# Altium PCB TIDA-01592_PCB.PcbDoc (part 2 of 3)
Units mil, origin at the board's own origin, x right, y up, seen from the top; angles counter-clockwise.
Board outline 2047.24 x 4291.34 mil, 4 copper layers (Top Layer, GND, PWR, Bottom Layer), stack 61.6 mil thick; 218 components, 89 nets, 503 pads, 366 vias.
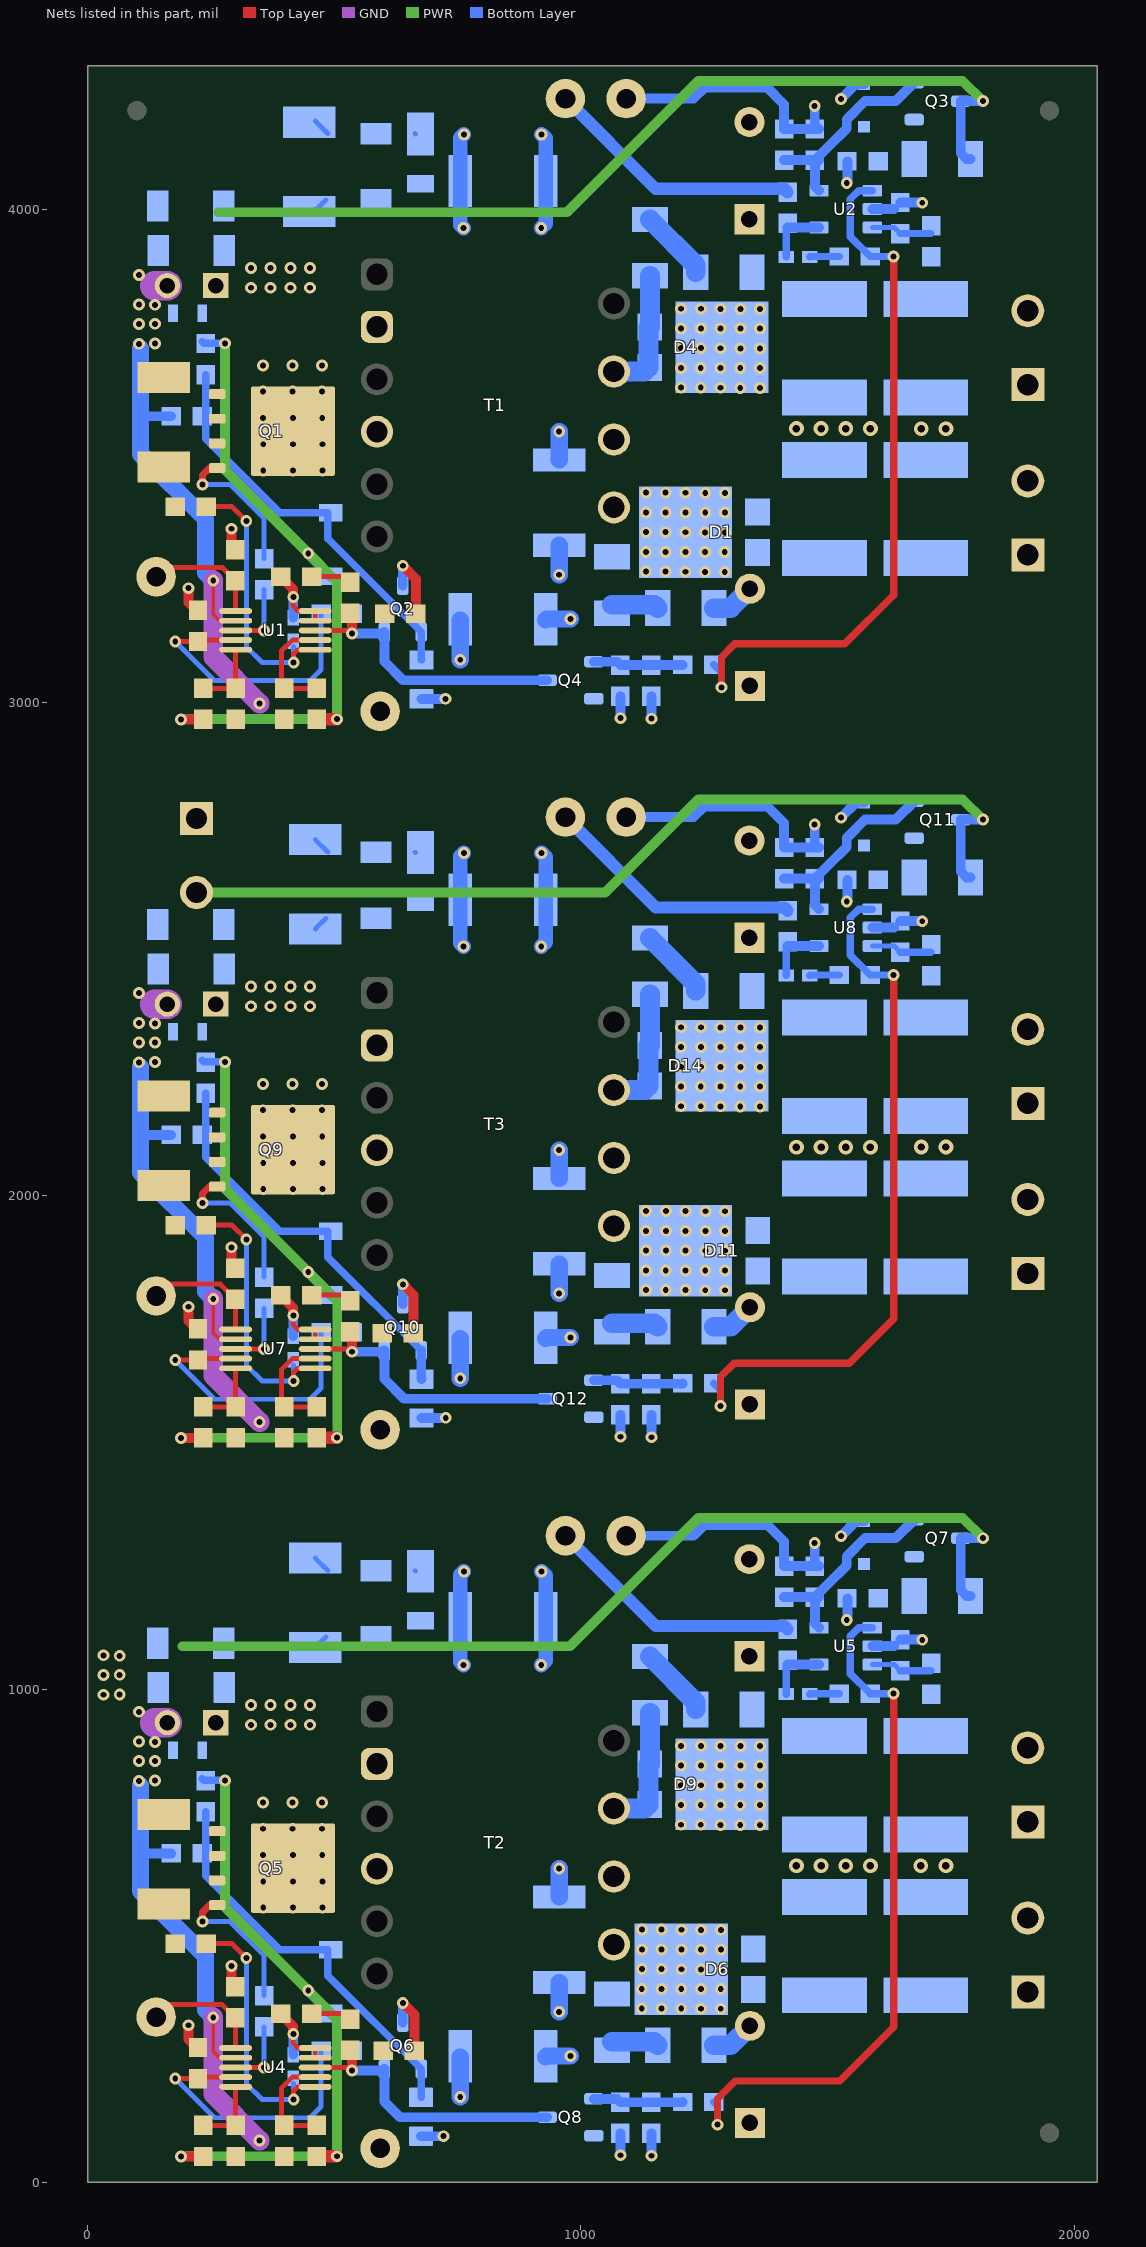
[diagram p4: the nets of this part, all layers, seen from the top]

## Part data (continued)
U2 U5 U8: "36V, Low-Power, RRO, General-Purpose Operational Amplifier, DBV0005A (SOT-23-5)", Alternate Manufacturer="Texas Instruments", Alternate PartNumber=TLV171IDBVT
ZZ1: library part AssemblyNoteLabel, Alternate Manufacturer=-
ZZ2 ZZ3 ZZ4: library part AssemblyNote, Alternate Manufacturer=-

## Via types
v1: diameter 24, hole 12, Top Layer to Bottom Layer, 348 vias
v2: diameter 30, hole 15, Top Layer to Bottom Layer, 18 vias

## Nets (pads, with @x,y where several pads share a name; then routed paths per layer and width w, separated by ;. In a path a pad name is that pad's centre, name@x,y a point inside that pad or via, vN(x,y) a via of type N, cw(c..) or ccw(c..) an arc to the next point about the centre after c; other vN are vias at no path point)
+Vo1: C31.1 C32.2 C33.2 C34.1 D9.3 J6.1 R39.2
  other v1: 1323.06,724.67 1363.06,724.67 1202.94,725 1242.94,725 1283,724.83 1323.06,764.67 1363.06,764.67 1202.94,765 1242.94,765 1283,764.83 1323.22,804.73 1363.22,804.73 1203.11,805.05 1243.11,805.05 1283.16,804.89 1203.27,845.11 1243.27,845.11 1283.32,844.94 1323.38,844.78 1363.38,844.78 1203.27,885.11 1243.27,885.11 1283.32,884.94 1323.38,884.78 1363.38,884.78
+Vo2: C52.1 C53.2 C54.2 C55.1 D14.3 J9.1 R68.2
  other v1: 1202.94,2181.69 1242.94,2181.69 1283,2181.53 1323.06,2181.37 1363.06,2181.37 1202.94,2221.69 1242.94,2221.69 1283,2221.53 1323.06,2221.37 1363.06,2221.37 1203.11,2261.74 1243.11,2261.74 1283.16,2261.58 1323.22,2261.42 1363.22,2261.42 1283.32,2301.64 1323.38,2301.48 1363.38,2301.48 1203.27,2301.8 1243.27,2301.8 1283.32,2341.64 1323.38,2341.48 1363.38,2341.48 1203.27,2341.8 1243.27,2341.8
+Vo3: C10.1 C11.2 C12.2 C13.1 D4.3 J3.1 R10.2
  other v1: 1202.94,3638.38 1242.94,3638.38 1283,3638.22 1323.06,3638.06 1363.06,3638.06 1202.94,3678.38 1242.94,3678.38 1283,3678.22 1323.06,3678.06 1363.06,3678.06 1203.11,3718.44 1243.11,3718.44 1283.16,3718.28 1323.22,3718.11 1363.22,3718.11 1203.27,3758.49 1243.27,3758.49 1283.32,3758.33 1323.38,3758.17 1363.38,3758.17 1203.27,3798.49 1243.27,3798.49 1283.32,3798.33 1323.38,3798.17 1363.38,3798.17
GND: C2.2 C3.2 C4.2 C9.1 C14.2 C18.2 C19.2 C20.1 C21.2 C23.2 C24.2 C25.2 C30.1 C35.2 C39.2 C40.2 C42.2 C44.2 C45.2 C46.2 C51.1 C56.2 C60.2 C61.2 C62.1 C63.2 C68.1 J1.1 Q2.3 Q6.3 Q10.3 R2.1 R8.1 R13.1 R14.1 R17.1 R20.1 R21.1 R25.1 R27.1 R31.1 R37.1 R42.1 R43.1 R49.1 R56.1 R60.1 R66.1 R71.1 R72.1 R78.1 R85.1 TP2.1 TP6.1 TP10.1 U1.4 U1.5 U1.7 U4.4 U4.5 U4.7 U7.4 U7.5 U7.7 | length 5332.4
  Top Layer w8: v1(254.69,334.05) 254.69,265.01 265.11,254.59 298.13,254.59 U4.7@300.03,252.68 ; v1(254.69,1790.74) 254.69,1721.7 265.11,1711.28 298.13,1711.28 U7.7@300.03,1709.38 ; v1(254.69,3247.43) 254.69,3178.39 265.11,3167.98 298.13,3167.98 U1.7@300.03,3166.07
  Top Layer w10: v1@416.68,301 416.68,282.32 426.63,272.37 U4.5@461.45,272.37 U4.4@461.45,252.68 ; v1@416.68,1757.69 416.68,1739.02 426.63,1729.06 U7.5@461.45,1729.06 U7.4@461.45,1709.38 ; v1@416.68,3214.39 416.68,3195.71 426.63,3185.76 U1.5@461.45,3185.76 U1.4@461.45,3166.07
  Top Layer w20: v1(204.26,318.5) 204.26,289.74 C40.2@220,274 ; v1(204.26,1775.2) 204.26,1746.43 C61.2@220,1730.69 ; v1(204.26,3231.89) 204.26,3203.13 C19.2@220,3187.39 ; v1(291.74,439) 291.74,404.5 R43.1@299.74,396.5 ; v1(291.74,1895.69) 291.74,1861.19 R72.1@299.74,1853.19 ; v1(291.74,3352.39) 291.74,3317.88 R14.1@299.74,3309.88 ; C30.1@300.74,52.5 C30.1@301.24,52 ; C51.1@300.74,1509.2 C51.1@301.24,1508.69 ; C9.1@300.74,2965.89 C9.1@301.24,2965.39 ; C42.2@391.24,342 416.68,316.57 416.68,301 v1(417,301) ; C63.2@391.24,1798.69 416.68,1773.26 416.68,1757.69 v1(417,1757.69) ; C21.2@391.24,3255.39 416.68,3229.95 416.68,3214.39 v1(417,3214.39) ; R37.1@398.24,52 R37.1@398.74,52.5 ; R66.1@398.24,1508.69 R66.1@398.74,1509.2 ; R8.1@398.24,2965.39 R8.1@398.74,2965.89 ; v1(639,364) 662.5,340.5 C62.1@662.5,267 ; v1(639,1820.69) 660.5,1799.2 C68.1@660.5,1721 ; v1(639,3277.39) 665.5,3250.89 C20.1@665.5,3180
  GND w40: v1(254.69,334.05) 254.69,179.05 v1(348.74,85) ; v1(254.69,1790.74) 254.69,1635.74 v1(348.74,1541.69) ; v1(254.69,3247.43) 254.69,3092.43 v1(348.74,2998.39)
  GND w60: C23.2@136.5,932 C23.2@161.53,932 ; C44.2@136.5,2388.69 C44.2@161.53,2388.69 ; C2.2@136.5,3845.39 C2.2@161.53,3845.39
  Bottom Layer w20: 107,666 108,667 R21.1@169.5,667 ; 107,2122.69 108,2123.69 R25.1@169.5,2123.69 ; 107,3579.39 108,3580.39 R17.1@169.5,3580.39 ; C39.2@417,258.62 v1(417,301) ; C60.2@417,1715.31 v1(417,1757.69) ; C18.2@417,3172.01 v1(417,3214.39) ; Q6.3@639,324.24 v1(639,364) ; Q10.3@639,1780.94 v1(639,1820.69) ; Q2.3@639,3237.63 v1(639,3277.39) ; C35.2@676,93.63 v1(721.63,93.63) ; C56.2@677,1549.63 684.37,1549.63 684.74,1550 v1(726,1550) ; C14.2@677,3007.63 v1(725.37,3007.63)
  Bottom Layer w30: v1(761.74,1049) 755.39,1055.35 R49.1@755.39,1144 755.39,1231.15 v1(762.74,1238.5) ; v1(761.74,2505.69) 755.39,2512.05 R78.1@755.39,2600.69 755.39,2687.84 v1(762.74,2695.2) ; v1(761.74,3962.39) 755.39,3968.74 R20.1@755.39,4057.39 755.39,4144.54 v1(762.74,4151.89)
  Bottom Layer w35: v1@107,804 107,666 107,590.74 239,458.74 239,349.74 v1(254.69,334.05) ; v1@107,2260.69 107,2122.69 107,2047.43 239,1915.43 239,1806.43 v1(254.69,1790.74) ; v1@107,3717.39 107,3579.39 107,3504.13 239,3372.13 239,3263.13 v1(254.69,3247.43) ; v1(755.39,173.39) R56.1@755.39,254 ; v1(755.39,1630.08) R85.1@755.39,1710.69 ; v1(755.39,3086.77) R27.1@755.39,3167.39
  other v1: 104,814 136.5,814.5 104,854 136.5,854.5 136.5,893 104,894 104,954 32.5,988.5 65,989 32.5,1028.5 65,1029 65,1067.5 32.5,1068.5 104,2270.69 136.5,2271.19 104,2310.69 136.5,2311.19 136.5,2349.69 104,2350.69 104,2411 104,3727.39 136.5,3727.88 104,3767.39 136.5,3767.88 136.5,3806.39 104,3807.39 104,3867
NetC1_1: C1.1 C5.1 C6.1 C7.2 D1.1 D1.2 J2.2 | length 89
  Bottom Layer w40: C1.1@1270.09,3191.39 1303.31,3191.39 C7.2@1342.74,3230.81
NetC1_2: C1.2 R1.2 | length 95.8
  Bottom Layer w40: R1.2@1063,3198.39 1148.91,3198.39 C1.2@1155.91,3191.39
NetC8_2: C8.2 D2.1 R3.1 | length 37.3
  Bottom Layer w10: R3.1@461.74,4178.94 R3.1@487.36,4153.31 ; D2.1@664.01,4153.31 D2.1@664.74,4152.58
NetC9_2: C9.2 R5.2 U1.10 | length 144.4
  Top Layer w10: R5.2@234.74,3028.88 C9.2@300.74,3028.88 300.03,3029.59 U1.10@300.03,3107.02
NetC10_2: C10.2 R7.2 | length 145.6
  Bottom Layer w40: R7.2@1140,3979.47 1232.91,3886.56 C10.2@1232.91,3872.39
NetC14_1: C14.1 D3.2 Q2.1 R6.1 R17.2 | length 816.8
  Bottom Layer w15: R6.1@239.71,3664.92 239.71,3534.68 389.53,3384.85 487,3384.85 487,3332.54 Q2.1@676.4,3143.14 676.4,3086.97 C14.1@677,3086.37
NetC15_1: C15.1 R28.1 U2.1 | length 1433
  Top Layer w15: v1(1285,3031) 1285,3092 1312,3119 1535,3119 1634,3218 v1(1634,3904.39)
  Bottom Layer w15: R28.1@1269.5,3076.39 1285,3060.88 v1(1285,3031) ; U2.1@1591.06,4037.98 1563.34,4037.98 1546.24,4020.88 1546.24,3944.65 C15.1@1586.5,3904.39 v1(1634,3904.39)
NetC15_2: C15.2 R19.1 | length 60.3
  Bottom Layer w15: R19.1@1463.62,3903.39 1464.62,3904.39 C15.2@1523.5,3904.39
NetC18_1: C18.1 R11.1 U1.1 | length 562.3
  Top Layer w10: R11.1@240.24,3397.39 R11.1@245.24,3397.39 ; R11.1@240.24,3402.39 R11.1@245.24,3397.39 ; v1(321.74,3368.39) 292.74,3397.39 R11.1@245.24,3397.39 ; v1(417.74,3081.39) 417.74,3099.39 425.37,3107.02 U1.1@461.45,3107.02
  Bottom Layer w10: v1(321.74,3368.39) 321.74,3113.39 353.74,3081.39 v1(417.74,3081.39) C18.1@417.74,3114.02
NetC19_1: C19.1 R12.2 U1.9 | length 574.7
  Top Layer w10: v1(177.74,3123.89) C19.1@223.74,3123.89 226.55,3126.7 U1.9@300.03,3126.7
  Bottom Layer w10: v1(177.74,3123.89) 257.24,3044.39 450.74,3044.39 473.24,3066.89 R12.2@473.24,3180.39
NetC20_2: C20.2 Q2.2 Q4.3 R12.1 R18.2 U1.3 | length 631
  Top Layer w10: U1.3@461.45,3146.39 v1@533.47,3146.39 ; R18.2@529.74,3190.89 R18.2@531.74,3192.89
  Top Layer w20: R18.2@532,3180.89 536.24,3176.65 536,3176.42 v1(536,3140)
  Bottom Layer w20: R12.1@536.24,3180.39 536,3180.15 v1(536,3140) 597.5,3140 601.12,3143.62 Q2.2@601.6,3143.14 601.6,3083.4 639.61,3045.39 Q4.3@931.76,3045.39
NetC21_1: C21.1 R18.1 | length 77.7
  Top Layer w10: C21.1@454.24,3255.39 454.73,3255.88 R18.1@531.74,3255.88
NetC22_1: C22.1 C26.1 C27.1 C28.2 D6.1 D6.2 J5.2 | length 89
  Bottom Layer w40: C22.1@1270.09,278 1303.31,278 C28.2@1342.74,317.43
NetC22_2: C22.2 R30.2 | length 95.8
  Bottom Layer w40: R30.2@1063,285 1148.91,285 C22.2@1155.91,278
NetC29_2: C29.2 D7.1 R32.1 | length 37.3
  Bottom Layer w10: R32.1@461.74,1265.55 R32.1@487.36,1239.93 ; D7.1@664.01,1239.93 D7.1@664.74,1239.2
NetC30_2: C30.2 R34.2 U4.10 | length 144.4
  Top Layer w10: R34.2@234.74,115.5 C30.2@300.74,115.5 300.03,116.2 U4.10@300.03,193.63
NetC31_2: C31.2 R36.2 | length 145.6
  Bottom Layer w40: R36.2@1140,1066.09 1232.91,973.17 C31.2@1232.91,959
NetC35_1: C35.1 D8.2 Q6.1 R21.2 R35.1 | length 817.3
  Bottom Layer w15: R35.1@239.71,751.54 239.71,621.29 389.53,471.47 487,471.47 487,419.16 Q6.1@676.4,229.76 676,229.35 C35.1@676,172.37
NetC36_1: C36.1 R57.1 U5.1 | length 1427.5
  Top Layer w15: v1(1277,117) 1277,169.54 1313.07,205.62 1524.62,205.62 1634,315 v1(1634,991)
  Bottom Layer w15: R57.1@1269.5,163 1277,155.5 v1(1277,117) ; U5.1@1591.06,1124.6 1563.34,1124.6 1546.24,1107.5 1546.24,1031.26 C36.1@1586.5,991 v1(1634,991)
NetC36_2: C36.2 R23.1 | length 60.3
  Bottom Layer w15: R23.1@1463.62,990 1464.62,991 C36.2@1523.5,991
NetC39_1: C39.1 R40.1 U4.1 | length 562.3
  Top Layer w10: R40.1@240.24,484 R40.1@245.24,484 ; R40.1@240.24,489 R40.1@245.24,484 ; v1(321.74,455) 292.74,484 R40.1@245.24,484 ; v1(417.74,168) 417.74,186 425.37,193.63 U4.1@461.45,193.63
  Bottom Layer w10: v1(321.74,455) 321.74,200 353.74,168 v1(417.74,168) C39.1@417.74,200.64
NetC40_1: C40.1 R41.2 U4.9 | length 574.7
  Top Layer w10: v1(177.74,210.5) C40.1@223.74,210.5 226.55,213.31 U4.9@300.03,213.31
  Bottom Layer w10: v1(177.74,210.5) 257.24,131 450.74,131 473.24,153.5 R41.2@473.24,267
NetC41_2: C41.2 Q4.1 R28.2 R29.1 | length 183.3
  Bottom Layer w20: Q4.1@1026.24,3082.79 1073.09,3082.79 R29.1@1080,3075.88 C41.2@1143,3075.88 1206,3075.88 R28.2@1206.5,3076.39
NetC42_1: C42.1 R47.1 | length 77.7
  Top Layer w10: C42.1@454.24,342 454.73,342.5 R47.1@531.74,342.5
NetC43_1: C43.1 C47.1 C48.1 C49.2 D11.1 D11.2 J8.2 | length 89
  Bottom Layer w40: C43.1@1270.09,1734.69 1303.31,1734.69 C49.2@1342.74,1774.12
NetC43_2: C43.2 R59.2 | length 95.8
  Bottom Layer w40: R59.2@1063,1741.69 1148.91,1741.69 C43.2@1155.91,1734.69
NetC50_2: C50.2 D12.1 R61.1 | length 37.3
  Bottom Layer w10: R61.1@461.74,2722.24 R61.1@487.36,2696.62 ; D12.1@664.01,2696.62 D12.1@664.74,2695.89
NetC51_2: C51.2 R63.2 U7.10 | length 144.4
  Top Layer w10: R63.2@234.74,1572.19 C51.2@300.74,1572.19 300.03,1572.9 U7.10@300.03,1650.32
NetC52_2: C52.2 R65.2 | length 145.6
  Bottom Layer w40: R65.2@1140,2522.78 1232.91,2429.87 C52.2@1232.91,2415.69
NetC56_1: C56.1 D13.2 Q10.1 R25.2 R64.1 | length 818.1
  Bottom Layer w15: R64.1@239.71,2208.23 239.71,2077.98 389.53,1928.16 487,1928.16 487,1875.85 Q10.1@676.4,1686.45
  Bottom Layer w20: Q10.1@676.4,1686.45 676.4,1628.97 C56.1@677,1628.37
NetC57_1: C57.1 R86.1 U8.1 | length 1439.4
  Top Layer w15: v1(1283,1574) 1283,1633 1311,1661 1544,1661 1634,1751 v1(1634,2447.69)
  Bottom Layer w15: R86.1@1269.5,1619.69 1283,1606.19 v1(1283,1574) ; U8.1@1591.06,2581.29 1563.34,2581.29 1546.24,2564.19 1546.24,2487.95 C57.1@1586.5,2447.69 v1(1634,2447.69)
NetC57_2: C57.2 R26.1 | length 60.3
  Bottom Layer w15: R26.1@1463.62,2446.69 1464.62,2447.69 C57.2@1523.5,2447.69
NetC60_1: C60.1 R69.1 U7.1 | length 562.3
  Top Layer w10: R69.1@240.24,1940.69 R69.1@245.24,1940.69 ; R69.1@240.24,1945.69 R69.1@245.24,1940.69 ; v1(321.74,1911.69) 292.74,1940.69 R69.1@245.24,1940.69 ; v1(417.74,1624.69) 417.74,1642.69 425.37,1650.32 U7.1@461.45,1650.32
  Bottom Layer w10: v1(321.74,1911.69) 321.74,1656.69 353.74,1624.69 v1(417.74,1624.69) C60.1@417.74,1657.33
NetC61_1: C61.1 R70.2 U7.9 | length 574.7
  Top Layer w10: v1(177.74,1667.2) C61.1@223.74,1667.2 226.55,1670.01 U7.9@300.03,1670.01
  Bottom Layer w10: v1(177.74,1667.2) 257.24,1587.69 450.74,1587.69 473.24,1610.2 R70.2@473.24,1723.69
NetC62_2: C62.2 Q6.2 Q8.3 R41.1 R47.2 U4.3 | length 634
  Top Layer w10: U4.3@461.45,233 v1@533.47,233 ; R47.2@529.74,277.5 R47.2@531.74,279.5
  Top Layer w20: R47.2@532,267.5 536.24,263.27 536,263.03 v1(536,227)
  Bottom Layer w20: R41.1@536.24,267 536,266.76 v1(536,227) 597.88,227 601.12,230.24 Q6.2@601.6,229.76 601.6,163.4 633,132 Q8.3@931.76,132
NetC63_1: C63.1 R76.1 | length 77.7
  Top Layer w10: C63.1@454.24,1798.69 454.73,1799.19 R76.1@531.74,1799.19
NetC64_1: C64.1 D5.1 Q3.1 R22.1
NetC65_1: C65.1 D10.1 Q7.1 R51.1
NetC66_1: C66.1 D15.1 Q11.1 R80.1
NetC67_2: C67.2 Q8.1 R57.2 R58.1 | length 183.3
  Bottom Layer w20: Q8.1@1026.24,169.4 1073.09,169.4 R58.1@1080,162.5 C67.2@1143,162.5 1206,162.5 R57.2@1206.5,163
NetC68_2: C68.2 Q10.2 Q12.3 R70.1 R76.2 U7.3 | length 628.4
  Top Layer w10: U7.3@461.45,1689.69 v1@533.47,1689.69 ; R76.2@529.74,1734.2 R76.2@531.74,1736.2
  Top Layer w20: R76.2@532,1724.2 536.24,1719.96 536,1719.72 v1(536,1684)
  Bottom Layer w20: R70.1@536.24,1723.69 536,1723.46 v1(536,1684) 598.19,1684 601.12,1686.93 Q10.2@601.6,1686.45 601.6,1628.4 641.31,1588.69 Q12.3@931.76,1588.69
NetC69_2: C69.2 Q12.1 R86.2 R87.1 | length 183.3
  Bottom Layer w20: Q12.1@1026.24,1626.09 1073.09,1626.09 R87.1@1080,1619.19 C69.2@1143,1619.19 1206,1619.19 R86.2@1206.5,1619.69
NetD1_3: D1.3 R1.1 T1.7
  other v1: 1131.62,3265.44 1171.62,3265.44 1211.68,3265.28 1251.73,3265.11 1291.73,3265.11 1131.62,3305.44 1171.62,3305.44 1211.68,3305.28 1251.73,3305.11 1291.73,3305.11 1131.78,3345.49 1171.78,3345.49 1211.84,3345.33 1251.89,3345.17 1291.89,3345.17 1131.94,3385.55 1171.94,3385.55 1212,3385.39 1252.06,3385.22 1292.06,3385.22 1131.94,3425.55 1171.94,3425.55 1212,3425.39 1252.06,3425.22 1292.06,3425.22
NetD2_2: D2.2 Q1.5 Q1.6 Q1.7 Q1.8 Q1.9@416.26,3550.39 T1.4
  other v1: 356,3470.39 416.26,3470.39 476,3470.39 356,3523.72 416.26,3523.72 476,3523.72 355.74,3577.05 416,3577.05 475.74,3577.05 355.48,3630.39 415.74,3630.39 475.48,3630.39 355.22,3683.72 415.48,3683.72 475.22,3683.72
NetD4_1: D4.1 D4.2 R7.1 T1.9 | length 259.4
  Bottom Layer w40: T1.9@1066.93,3671.26 1128.76,3671.26 1137,3679.5 D4.1@1137,3761.39 ; D4.1@1139.95,3761.33 1139.95,3865.25 R7.1@1140,3865.3
NetD6_3: D6.3 R30.1 T2.7
  other v1: 1123.38,352.26 1163.38,352.26 1203.43,352.09 1243.49,351.93 1283.49,351.93 1123.38,392.26 1163.38,392.26 1203.43,392.09 1243.49,391.93 1283.49,391.93 1123.54,432.31 1163.54,432.31 1203.59,432.15 1243.65,431.99 1283.65,431.99 1123.7,472.37 1163.7,472.37 1203.76,472.2 1243.81,472.04 1283.81,472.04 1123.7,512.37 1163.7,512.37 1203.76,512.2 1243.81,512.04 1283.81,512.04
NetD7_2: D7.2 Q5.5 Q5.6 Q5.7 Q5.8 Q5.9@416.26,637 T2.4
  other v1: 356,557 416.26,557 476,557 356,610.33 416.26,610.33 476,610.33 355.74,663.67 416,663.67 475.74,663.67 355.48,717 415.74,717 475.48,717 355.22,770.33 415.48,770.33 475.22,770.33
NetD9_1: D9.1 D9.2 R36.1 T2.9 | length 259.4
  Bottom Layer w40: T2.9@1066.93,757.87 1128.76,757.87 1137,766.11 D9.1@1137,848 ; D9.1@1139.95,847.94 1139.95,951.87 R36.1@1140,951.91
NetD11_3: D11.3 R59.1 T3.7
  other v1: 1252.11,1808.68 1292.11,1808.68 1132,1809 1172,1809 1212.06,1808.84 1252.11,1848.68 1292.11,1848.68 1132,1849 1172,1849 1212.06,1848.84 1252.27,1888.73 1292.27,1888.73 1132.16,1889.06 1172.16,1889.06 1212.22,1888.89 1132.32,1929.11 1172.32,1929.11 1212.38,1928.95 1252.43,1928.79 1292.43,1928.79 1132.32,1969.11 1172.32,1969.11 1212.38,1968.95 1252.43,1968.79 1292.43,1968.79
NetD12_2: D12.2 Q9.5 Q9.6 Q9.7 Q9.8 Q9.9@416.26,2093.69 T3.4
  other v1: 356,2013.69 416.26,2013.69 476,2013.69 356,2067.03 416.26,2067.03 476,2067.03 355.74,2120.36 416,2120.36 475.74,2120.36 355.48,2173.69 415.74,2173.69 475.48,2173.69 355.22,2227.03 415.48,2227.03 475.22,2227.03
NetD14_1: D14.1 D14.2 R65.1 T3.9 | length 259.4
  Bottom Layer w40: T3.9@1066.93,2214.57 1128.76,2214.57 1137,2222.8 D14.1@1137,2304.69 ; D14.1@1139.95,2304.64 1139.95,2408.56 R65.1@1140,2408.61
NetQ1_1: Q1.1 Q1.2 Q1.3 R11.2 R13.2
NetQ1_4: Q1.4 R9.2 | length 288.9
  Top Layer w15: v1(233,3442.39) 233,3461.39 247,3475.39 Q1.4@262.72,3475.39
  Bottom Layer w10: v1(233,3442.39) 288,3442.39 357.74,3372.65 R9.2@357.74,3291.88
NetQ5_1: Q5.1 Q5.2 Q5.3 R40.2 R42.2
NetQ5_4: Q5.4 R38.2 | length 288.9
  Top Layer w15: v1(233,529) 233,548 247,562 Q5.4@262.72,562
  Bottom Layer w10: v1(233,529) 288,529 357.74,459.26 R38.2@357.74,378.5
NetQ9_1: Q9.1 Q9.2 Q9.3 R69.2 R71.2
NetQ9_4: Q9.4 R67.2 | length 288.9
  Top Layer w15: v1(233,1985.69) 233,2004.69 247,2018.69 Q9.4@262.72,2018.69
  Bottom Layer w10: v1(233,1985.69) 288,1985.69 357.74,1915.95 R67.2@357.74,1835.19
NetR4_1: R4.1 R8.2 U1.2 | length 221.8
  Top Layer w10: U1.2@461.45,3126.7 415.06,3126.7 392.87,3104.51 392.87,3034.76 R8.2@398.74,3028.88 R4.1@464.74,3028.88
NetR9_1: R9.1 U1.8 | length 140.2
  Top Layer w10: U1.8@300.03,3146.39 v1(357.74,3146.39)
  Bottom Layer w10: v1(357.74,3146.39) R9.1@357.74,3228.89
NetR10_1: R10.1 R16.1 U2.3 | length 123.8
  Bottom Layer w10: U2.3@1591.06,3963.18 1635.45,3963.18 R16.1@1647.74,3950.89
  Bottom Layer w15: R16.1@1647.74,3950.89 R10.1@1709.74,3950.89
NetR14_2: R14.2 TP1.1 U1.6 | length 241.1
  Top Layer w10: TP1.1@139,3255 158,3274 272.63,3274 R14.2@299.74,3246.89 300.03,3246.6 U1.6@300.03,3185.76
NetR15_1: R15.1 R19.2 U2.4 | length 124.7
  Bottom Layer w15: R19.2@1416.38,3903.39 1416.38,3960.53 R15.1@1418.74,3962.89
  Bottom Layer w20: R15.1@1418.74,3962.89 1419.03,3963.18 U2.4@1482.79,3963.18
NetR23_2: R23.2 R44.1 U5.4 | length 124.7
  Bottom Layer w15: R23.2@1416.38,990 1416.38,1047.14 R44.1@1418.74,1049.5
  Bottom Layer w20: R44.1@1418.74,1049.5 1419.03,1049.79 U5.4@1482.79,1049.79
NetR26_2: R26.2 R73.1 U8.4 | length 124.7
  Bottom Layer w15: R26.2@1416.38,2446.69 1416.38,2503.83 R73.1@1418.74,2506.2
  Bottom Layer w20: R73.1@1418.74,2506.2 1419.03,2506.49 U8.4@1482.79,2506.49
NetR33_1: R33.1 R37.2 U4.2 | length 221.8
  Top Layer w10: U4.2@461.45,213.31 415.06,213.31 392.87,191.13 392.87,121.37 R37.2@398.74,115.5 R33.1@464.74,115.5
NetR38_1: R38.1 U4.8 | length 140.2
  Top Layer w10: U4.8@300.03,233 v1(357.74,233)
  Bottom Layer w10: v1(357.74,233) R38.1@357.74,315.5
NetR39_1: R39.1 R45.1 U5.3 | length 123.8
  Bottom Layer w10: U5.3@1591.06,1049.79 1635.45,1049.79 R45.1@1647.74,1037.5
  Bottom Layer w15: R45.1@1647.74,1037.5 R39.1@1709.74,1037.5
NetR43_2: R43.2 TP5.1 U4.6 | length 244.2
  Top Layer w10: TP5.1@139,335 165,361 272.24,361 R43.2@299.74,333.5 300.03,333.21 U4.6@300.03,272.37
NetR62_1: R62.1 R66.2 U7.2 | length 221.8
  Top Layer w10: U7.2@461.45,1670.01 415.06,1670.01 392.87,1647.82 392.87,1578.06 R66.2@398.74,1572.19 R62.1@464.74,1572.19
NetR67_1: R67.1 U7.8 | length 140.2
  Top Layer w10: U7.8@300.03,1689.69 v1(357.74,1689.69)
  Bottom Layer w10: v1(357.74,1689.69) R67.1@357.74,1772.2
NetR68_1: R68.1 R74.1 U8.3 | length 123.8
  Bottom Layer w10: U8.3@1591.06,2506.49 1635.45,2506.49 R74.1@1647.74,2494.2
  Bottom Layer w15: R74.1@1647.74,2494.2 R68.1@1709.74,2494.2
NetR72_2: R72.2 TP9.1 U7.6 | length 244.7
  Top Layer w10: TP9.1@139,1797 162.97,1820.97 268.97,1820.97 R72.2@299.74,1790.2 300.03,1789.91 U7.6@300.03,1729.06
PWRGND01: C37.2 C38.2 C65.2 C67.1 D10.2 Q8.2 R45.2 R53.1 R56.2 R58.2 TP8.1 U5.2 | length 916.4
  Bottom Layer w10: R45.2@1634.44,1087.2 R45.2@1647.74,1100.5
  Bottom Layer w20: v1(1080,55) R58.2@1080,99.5 ; TP8.1@1091.74,1311 1228.37,1311 1250.37,1333 1378.37,1333 1412,1299.37 C37.2@1412,1249.5 ; v1(1143,54) C67.1@1143,99.5 ; C37.2@1417.74,1249.5 C38.2@1474,1249.5 ; v1(1474,1296) C38.2@1474,1249.5 ; C38.2@1482.74,1249.5 C38.2@1474,1249.5 ; v1(1527,1310) 1557.31,1340.31 D10.2@1574,1340.31 ; v1(1539,1140) 1540.5,1141.5 C65.2@1540.5,1184 ; U5.2@1591.06,1087.2 R45.2@1634.44,1087.2 ; R45.2@1647.74,1100.5 1691.5,1100.5 v1(1692,1100)
  Bottom Layer w35: R56.2@928.61,254 930.61,256 v1(979,256) ; v1(956,345.76) R53.1@956,405.39
PWRGND02: C58.2 C59.2 C66.2 C69.1 D15.2 Q12.2 R74.2 R82.1 R85.2 R87.2 TP12.1 U8.2 | length 916.4
  Bottom Layer w10: R74.2@1634.44,2543.89 R74.2@1647.74,2557.19
  Bottom Layer w20: v1(1080,1511.69) R87.2@1080,1556.2 ; TP12.1@1091.74,2767.69 1228.37,2767.69 1250.37,2789.69 1378.37,2789.69 1412,2756.06 C58.2@1412,2706.19 ; v1(1143,1510.69) C69.1@1143,1556.2 ; C58.2@1417.74,2706.19 C59.2@1474,2706.19 ; v1(1474,2752.69) C59.2@1474,2706.19 ; C59.2@1482.74,2706.19 C59.2@1474,2706.19 ; v1(1527,2766.69) 1557.31,2797 D15.2@1574,2797 ; v1(1539,2596.69) 1540.5,2598.2 C66.2@1540.5,2640.69 ; U8.2@1591.06,2543.89 R74.2@1634.44,2543.89 ; R74.2@1647.74,2557.19 1691.5,2557.19 v1(1692,2556.69)
  Bottom Layer w35: R85.2@928.61,1710.69 930.61,1712.69 v1(979,1712.69) ; v1(956,1802.46) R82.1@956,1862.08
PWRGND03: C16.2 C17.2 C41.1 C64.2 D5.2 Q4.2 R16.2 R24.1 R27.2 R29.2 TP4.1 U2.2 | length 916.4
  Bottom Layer w10: R16.2@1634.44,4000.58 R16.2@1647.74,4013.88
  Bottom Layer w20: v1(1080,2968.39) R29.2@1080,3012.89 ; TP4.1@1091.74,4224.39 1228.37,4224.39 1250.37,4246.39 1378.37,4246.39 1412,4212.76 C16.2@1412,4162.88 ; v1(1143,2967.39) C41.1@1143,3012.89 ; C16.2@1417.74,4162.88 C17.2@1474,4162.88 ; v1(1474,4209.39) C17.2@1474,4162.88 ; C17.2@1482.74,4162.88 C17.2@1474,4162.88 ; v1(1527,4223.39) 1557.31,4253.69 D5.2@1574,4253.69 ; v1(1539,4053.39) 1540.5,4054.89 C64.2@1540.5,4097.39 ; U2.2@1591.06,4000.58 R16.2@1634.44,4000.58 ; R16.2@1647.74,4013.88 1691.5,4013.88 v1(1692,4013.39)
  Bottom Layer w35: R27.2@928.61,3167.39 930.61,3169.39 v1(979,3169.39) ; v1(956,3259.15) R24.1@956,3318.77
PWRGND11: C26.2 C27.2 C28.1 C32.1 C33.1 C34.2 J5.1 J6.2 R49.2 R53.2 T2.8 | length 254
  Bottom Layer w30: v1(919.72,1049) 928.61,1057.89 R49.2@928.61,1144 928.61,1230.11 v1(920.22,1238.5)
  Bottom Layer w35: R53.2@956,578.61 v1(956,636)
  other v2: 1437,642 1487,642 1537,642 1587,642 1689,642 1740,642
PWRGND12: C47.2 C48.2 C49.1 C53.1 C54.1 C55.2 J8.1 J9.2 R78.2 R82.2 T3.8 | length 254
  Bottom Layer w30: v1(919.72,2505.69) 928.61,2514.58 R78.2@928.61,2600.69 928.61,2686.8 v1(920.22,2695.2)
  Bottom Layer w35: R82.2@956,2035.31 v1(956,2092.69)
  other v2: 1437,2098.69 1487,2098.69 1537,2098.69 1587,2098.69 1690,2099 1740,2099
PWRGND13: C5.2 C6.2 C7.1 C11.1 C12.1 C13.2 J2.1 J3.2 R20.2 R24.2 T1.8 | length 254
  Bottom Layer w30: v1(919.72,3962.39) 928.61,3971.28 R20.2@928.61,4057.39 928.61,4143.5 v1(920.22,4151.89)
  Bottom Layer w35: R24.2@956,3492 v1(956,3549.39)
  other v2: 1437,3555.39 1487,3555.39 1537,3555.39 1587,3555.39 1690,3555 1740,3555
VCONT1: R44.2 TP7.1 | length 528.8
  Bottom Layer w25: TP7.1@968.74,1311 1151.74,1128 1412.5,1128 R44.2@1419,1121.5
VCONT2: R73.2 TP11.1 | length 528.8
  Bottom Layer w25: TP11.1@968.74,2767.69 1151.74,2584.69 1412.5,2584.69 R73.2@1419,2578.19
VCONT3: R15.2 TP3.1 | length 528.8
  Bottom Layer w25: TP3.1@968.74,4224.39 1151.74,4041.39 1412.5,4041.39 R15.2@1419,4034.88
Vin: C2.1 C3.1 C4.1 C8.1 C23.1 C24.1 C25.1 C29.1 C44.1 C45.1 C46.1 C50.1 D3.1 D8.1 D13.1 J1.2 Q3.3 Q7.3 Q11.3 R2.2 R3.2 R4.2 R5.1 R6.2 R22.2 R31.2 R32.2 R33.2 R34.1 R35.2 R51.2 R60.2 R61.2 R62.2 R63.1 R64.2 R80.2 T1.2 T2.2 T3.2 | length 9816.8
  Top Layer w20: v1(189.24,52.5) R34.1@234.74,52.5 ; v1(189.24,1509.2) R63.1@234.74,1509.2 ; v1(189.24,2965.89) R5.1@234.74,2965.89
  Top Layer w25: R33.2@464.74,52.5 465.24,53 v1(505.74,53) ; R62.2@464.74,1509.2 465.24,1509.69 v1(505.74,1509.69) ; R4.2@464.74,2965.89 465.24,2966.39 v1(505.74,2966.39)
  PWR w20: v1(189.24,52.5) 189.74,53 v1(505.74,53) ; v1(189.24,1509.2) 189.74,1509.69 v1(505.74,1509.69) ; v1(189.24,2965.89) 189.74,2966.39 v1(505.74,2966.39) ; 192,1087 978,1087 1238,1347 1774,1347 v1(1815,1306) ; J1.2@220.74,2615 1049.31,2615 1238,2803.69 1774,2803.69 v1(1815,2762.69) ; 265,3994 971.61,3994 1238,4260.39 1774,4260.39 v1(1815,4219.39) ; v1(278.74,815) 278.74,557.76 v1(447.25,389.25) 505.74,330.76 v1@505.74,63.75 ; v1(278.74,2271.69) 278.74,2014.46 v1(447.25,1845.94) 506.13,1787.07 506.13,1520.83 v1@505.74,1520.44 ; v1(278.74,3728.39) 278.74,3471.15 v1(447.25,3302.64) 505.74,3244.15 v1@505.74,2977.13
  Bottom Layer w10: R32.2@461.74,1084.45 R32.2@483.36,1106.07 ; R61.2@461.74,2541.14 R61.2@483.36,2562.76 ; R3.2@461.74,3997.83 R3.2@483.36,4019.46
  Bottom Layer w15: R35.2@232.27,817.97 235.24,815 v1(278.74,815) ; R64.2@232.27,2274.66 235.24,2271.69 v1(278.74,2271.69) ; R6.2@232.27,3731.35 235.24,3728.39 v1(278.74,3728.39)
  Bottom Layer w20: v1(447.25,389.25) 447.25,388.28 D8.1@493,342.53 ; v1(447.25,1845.94) 447.25,1844.97 D13.1@493,1799.22 ; v1(447.25,3302.64) 447.25,3301.67 D3.1@493,3255.92 ; R51.2@1790.09,1189 1782,1189 1770.24,1200.76 Q7.3@1770.24,1306 v1(1815,1306) ; R80.2@1790.09,2645.69 1782,2645.69 1770.24,2657.45 Q11.3@1770.24,2762.69 v1(1815,2762.69) ; R22.2@1790.09,4102.39 1782,4102.39 1770.24,4114.14 Q3.3@1770.24,4219.39 v1(1815,4219.39)
  other v1: 331,927.61 371,927.61 411,927.61 451,927.61 331,967.61 371,967.61 411,967.61 451,967.61 331,2384.31 371,2384.31 411,2384.31 451,2384.31 331,2424.31 371,2424.31 411,2424.31 451,2424.31 331,3841 371,3841 411,3841 451,3841 331,3881 371,3881 411,3881 451,3881
VOPAMP1: C37.1 C38.1 Q7.2 U5.5 | length 416.9
  Bottom Layer w20: C37.1@1411.5,1187 C37.1@1412,1186.5 C38.1@1474,1186.5 C38.1@1474.5,1186.5 ; U5.5@1482.79,1124.6 1474.67,1132.72 1474.67,1178.44 1482.74,1186.5 C38.1@1474.5,1186.5 ; Q7.2@1675.76,1343.4 1638.35,1306 1576,1306 1539,1269 1539,1250.83 1500.1,1211.94 1499.94,1211.94 C38.1@1474.5,1186.5
VOPAMP2: C58.1 C59.1 Q11.2 U8.5 | length 416.9
  Bottom Layer w20: C58.1@1411.5,2643.69 C58.1@1412,2643.2 C59.1@1474,2643.2 C59.1@1474.5,2643.2 ; U8.5@1482.79,2581.29 1474.67,2589.41 1474.67,2635.13 1482.74,2643.2 C59.1@1474.5,2643.2 ; Q11.2@1675.76,2800.09 1638.35,2762.69 1576,2762.69 1539,2725.69 1539,2707.53 1500.1,2668.63 1499.94,2668.63 C59.1@1474.5,2643.2
VOPAMP3: C16.1 C17.1 Q3.2 U2.5 | length 416.9
  Bottom Layer w20: C16.1@1411.5,4100.39 C16.1@1412,4099.89 C17.1@1474,4099.89 C17.1@1474.5,4099.89 ; U2.5@1482.79,4037.98 1474.67,4046.1 1474.67,4091.82 1482.74,4099.89 C17.1@1474.5,4099.89 ; Q3.2@1675.76,4256.79 1638.35,4219.39 1576,4219.39 1539,4182.39 1539,4164.22 1500.1,4125.32 1499.94,4125.32 C17.1@1474.5,4099.89
pads on no net: FID1.1 FID2.1 FID3.1 FID4.1 FID5.1 FID6.1 Q1.9@366.65,3492.51 Q1.9@366.65,3550.39 Q1.9@366.65,3608.26 Q1.9@432.8,3492.51 Q1.9@432.8,3550.39 Q1.9@432.8,3608.26 Q5.9@366.65,579.13 Q5.9@366.65,637 Q5.9@366.65,694.87 Q5.9@432.8,579.13 Q5.9@432.8,637 Q5.9@432.8,694.87 Q9.9@366.65,2035.82 Q9.9@366.65,2093.69 Q9.9@366.65,2151.57 Q9.9@432.8,2035.82 Q9.9@432.8,2093.69 Q9.9@432.8,2151.57 T1.1 T1.3 T1.5 T1.6 T1.10 T2.1 T2.3 T2.5 T2.6 T2.10 T3.1 T3.3 T3.5 T3.6 T3.10

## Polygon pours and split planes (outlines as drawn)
GND on Top Layer "Top Layer-No Net 4" (solid, pour order 1178): 78.74,3645.65 97,3627.39 208.7,3627.39 240.74,3659.43 240.74,3758.91 197.74,3801.91 197.74,3891.39 177.74,3911.39 100,3911.39 78.74,3890.13
NetD2_2 on Top Layer "Top Layer-No Net" (solid, remove dead copper, pour order 1176): 327.74,3320.19 356.54,3291.39 716,3291.39 784,3359.39 784,3667.6 743.21,3708.39 500,3708.38 411,3797.39 341,3797.39 327.74,3784.13
PWRGND03 on Top Layer "PWR-No Net 1" (solid, remove dead copper, pour order 1172): 1720.08,4276.04 1757.74,4238.39 1757.74,3050.74 1635.68,2928.68 903.45,2928.68 886.74,2945.39 886.74,3269.39 886.74,4212.74 951.07,4277.07
Vin on Top Layer "Bottom Layer-No Net 2" (solid, remove dead copper, pour order 1170): 210.74,3716.39 220.74,3706.39 275.74,3706.39 291.74,3722.39 291.74,3810.39 298.74,3817.39 428.74,3817.39 517.74,3728.39 598.74,3728.39 621.74,3751.39 621.74,4037.39 569.74,4089.39 237,4089.39 210.74,4063.13 210.74,3995.39
GND on Top Layer "Top Layer-No Net 4" (solid, pour order 1124): 78.74,2188.95 97,2170.69 208.7,2170.69 240.74,2202.73 240.74,2302.22 197.74,2345.22 197.74,2434.69 177.74,2454.69 100,2454.69 78.74,2433.43
NetD12_2 on Top Layer "Top Layer-No Net" (solid, remove dead copper, pour order 1122): 327.74,1863.5 356.54,1834.69 716,1834.69 784,1902.69 784,2210.91 743.21,2251.7 500,2251.69 411,2340.69 341,2340.69 327.74,2327.43
PWRGND02 on Top Layer "PWR-No Net 1" (solid, remove dead copper, pour order 1118): 1720.08,2819.35 1757.74,2781.69 1757.74,1594.05 1635.68,1471.99 903.45,1471.99 886.74,1488.69 886.74,1812.69 886.74,2756.05 951.07,2820.38
Vin on Top Layer "Bottom Layer-No Net 2" (solid, remove dead copper, pour order 1116): 210.74,2259.69 220.74,2249.69 275.74,2249.69 291.74,2265.69 291.74,2353.69 298.74,2360.69 428.74,2360.69 517.74,2271.69 598.74,2271.69 621.74,2294.69 621.74,2580.69 569.74,2632.69 237,2632.69 210.74,2606.43 210.74,2538.69
Vin on Top Layer "Bottom Layer-No Net 2" (solid, remove dead copper, pour order 698): 210.74,803 220.74,793 275.74,793 291.74,809 291.74,897 298.74,904 428.74,904 517.74,815 598.74,815 621.74,838 621.74,1124 569.74,1176 237,1176 210.74,1149.74 210.74,1082
PWRGND01 on Top Layer "PWR-No Net 1" (solid, remove dead copper, pour order 674): 1720.08,1362.66 1757.74,1325 1757.74,137.35 1635.68,15.29 903.45,15.29 886.74,32 886.74,356 886.74,1299.35 951.07,1363.69
NetD7_2 on Top Layer "Top Layer-No Net" (solid, pour order 502): 327.74,406.8 356.54,378 716,378 784,446 784,754.22 743.21,795.01 500,795 411,884 341,884 327.74,870.74
NetC20_2 on Top Layer "Top Layer-No Net 2" (solid, remove dead copper, pour order 1182): 507,3141.39 521.39,3127 596,3127 625,3156 625,3200.39 512,3200.39 507,3195.39
GND on Top Layer "Top Layer-No Net 3" (solid, remove dead copper, pour order 1180): 279.74,2946.39 284.74,2941.39 416.74,2941.39 420.74,2945.39 420.74,2986.39 416.74,2990.39 378.74,2990.39 358.74,3010.39 340.74,3010.39 320.74,2990.39 284.74,2990.39 279.74,2985.39
NetQ1_1 on Top Layer "Top Layer-No Net 1" (solid, remove dead copper, pour order 1174): 304.74,3511.39 297.74,3504.39 248.74,3504.39 210.74,3466.39 210.74,3389.39 193.74,3372.39 106.74,3372.39 78.74,3400.39 78.74,3492.39 224.74,3638.39 299.74,3638.39 304.74,3633.39
NetC68_2 on Top Layer "Top Layer-No Net 2" (solid, remove dead copper, pour order 1128): 507,1684.69 521.69,1670 588,1670 617,1699 617,1743.69 512,1743.69 507,1738.69
GND on Top Layer "Top Layer-No Net 3" (solid, remove dead copper, pour order 1126): 279.74,1489.69 284.74,1484.69 416.74,1484.69 420.74,1488.69 420.74,1529.69 416.74,1533.69 378.74,1533.69 358.74,1553.69 340.74,1553.69 320.74,1533.69 284.74,1533.69 279.74,1528.69
NetQ9_1 on Top Layer "Top Layer-No Net 1" (solid, remove dead copper, pour order 1120): 304.74,2054.69 297.74,2047.69 248.74,2047.69 210.74,2009.69 210.74,1932.69 193.74,1915.69 106.74,1915.69 78.74,1943.69 78.74,2035.69 224.74,2181.69 299.74,2181.69 304.74,2176.69
NetQ5_1 on Top Layer "Top Layer-No Net 1" (solid, pour order 504): 304.74,598 297.74,591 248.74,591 210.74,553 210.74,476 193.74,459 106.74,459 78.74,487 78.74,579 224.74,725 299.74,725 304.74,720
GND on Top Layer "Top Layer-No Net 4" (solid, pour order 500): 78.74,732.26 97,714 208.7,714 240.74,746.04 240.74,845.53 197.74,888.53 197.74,978 177.74,998 118,998 78.74,958.74
GND on Top Layer "Top Layer-No Net 3" (solid, remove dead copper, pour order 498): 279.74,33 284.74,28 416.74,28 420.74,32 420.74,73 416.74,77 378.74,77 358.74,97 340.74,97 320.74,77 284.74,77 279.74,72
NetC62_2 on Top Layer "Top Layer-No Net 2" (solid, remove dead copper, pour order 496): 507,228 521,214 594,214 621,241 621,287 512,287 507,282
Vin on Bottom Layer "Bottom Layer-No Net 2" (solid, remove dead copper, pour order 1258): 210.74,2259.69 220.74,2249.69 275.74,2249.69 291.74,2265.69 291.74,2353.69 298.74,2360.69 428.74,2360.69 517.74,2271.69 598.74,2271.69 621.74,2294.69 621.74,2580.69 569.74,2632.69 253.31,2632.69 235,2651 206,2651 186,2631 186,2600 210.74,2575.26 210.74,2538.69
NetD2_2 on Bottom Layer "NETD2_2_L04_P1202" (solid, remove dead copper, pour order 1202): 641.74,3605.39 624.74,3588.39 563.74,3588.39 533.74,3558.39 533.74,3326.39 562.74,3297.39 705.74,3297.39 721.74,3313.39 721.74,4059.39 704.74,4076.39 641.74,4076.39
Vin on Bottom Layer "Bottom Layer-No Net 2" (solid, remove dead copper, pour order 1196): 210.74,3716.39 220.74,3706.39 275.74,3706.39 291.74,3722.39 291.74,3810.39 298.74,3817.39 428.74,3817.39 517.74,3728.39 598.74,3728.39 621.74,3751.39 621.74,4037.39 569.74,4089.39 237,4089.39 210.74,4063.13 210.74,3995.39
NetD12_2 on Bottom Layer "NETD12_2_L04_P1148" (solid, remove dead copper, pour order 1148): 641.74,2148.69 624.74,2131.69 563.74,2131.69 533.74,2101.69 533.74,1869.69 562.74,1840.69 705.74,1840.69 721.74,1856.69 721.74,2602.69 704.74,2619.69 641.74,2619.69
Vin on Bottom Layer "Bottom Layer-No Net 2" (solid, remove dead copper, pour order 514): 210.74,803 220.74,793 275.74,793 291.74,809 291.74,897 298.74,904 428.74,904 517.74,815 598.74,815 621.74,838 621.74,1124 569.74,1176 237,1176 210.74,1149.74 210.74,1082
NetD7_2 on Bottom Layer "NETD7_2_L04_P506" (solid, remove dead copper, pour order 506): 641.74,692 624.74,675 563.74,675 533.74,645 533.74,413 562.74,384 705.74,384 721.74,400 721.74,1146 704.74,1163 641.74,1163
PWRGND11 on Bottom Layer "Bottom Layer-No Net 11" (solid, remove dead copper, pour order 1256): 1063,554 896.61,554 887,563.61 887,1238.61 903,1254.61 977,1254.61 1016,1215.61 1016,701.61 1024.61,693 1063,693
PWRGND12 on Bottom Layer "Bottom Layer-No Net 11" (solid, remove dead copper, pour order 1254): 1063,2010.69 896.61,2010.69 887,2020.31 887,2695.31 903,2711.31 977,2711.31 1016,2672.31 1016,2158.31 1024.61,2149.69 1063,2149.69
PWRGND13 on Bottom Layer "Bottom Layer-No Net 11" (solid, remove dead copper, pour order 1252): 1063,3467.39 896.61,3467.39 887,3477 887,4152 903,4168 977,4168 1016,4129 1016,3615 1024.61,3606.39 1063,3606.39
PWRGND12 on Bottom Layer "Bottom Layer-No Net 4" (solid, remove dead copper, pour order 1248): 1373,2149.69 1391.85,2149.69 1407.15,2165 1407.15,2198.85 1412,2203.69 1780.64,2203.69 1799,2185.33 1799,2000.69 1780,1981.69 1412,1981.69 1383,2010.69 1055,2010.69 1033,2032.69 1033,2119.69 1063,2149.69
GND on Bottom Layer "Bottom Layer-No Net 10" (solid, remove dead copper, pour order 1224): 172,958 188,942 188,921 173,906 29,906 0,935 0,3834 38,3872 174,3872 187,3859 187,3832 174,3819 85,3819 81,3815 81,2860 134,2807 250,2807 266,2791 266,2736 246,2716 144,2716 81,2653 81,2418 84,2415 172,2415 188,2399 188,2378 172,2362 84,2362 81,2359 81,961 84,958
NetC64_1 on Bottom Layer "Bottom Layer-No Net 8" (solid, remove dead copper, pour order 1204): 1560,4146.39 1580,4126.39 1580,4077.39 1595,4062.39 1700,4062.39 1705,4067.38 1705,4183.24 1691.85,4196.39 1578,4196.39 1560,4178.39
NetC8_2 on Bottom Layer "NETC8_2_L04_P1200" (solid, remove dead copper, pour order 1200): 398.74,4132.39 423.74,4107.39 702.74,4107.39 712.74,4117.39 712.74,4205.39 699.74,4218.39 415.74,4218.39 398.74,4201.39
GND on Bottom Layer "Bottom Layer-No Net" (solid, remove dead copper, pour order 1198): 194.74,3708.39 190.74,3704.39 95.61,3704.39 89,3711 89,4062.39 175,4062.39 194.74,4042.65
NetD1_3 on Bottom Layer "Bottom Layer-No Net 3" (solid, remove dead copper, pour order 1194): 1031.74,3254.65 1037,3249.39 1289.28,3249.39 1300,3260.11 1300,3432.52 1293.13,3439.39 1040.74,3439.39 1031.74,3430.39
NetC1_1 on Bottom Layer "Bottom Layer-No Net 6" (solid, remove dead copper, pour order 1188): 1320,3255.39 1296,3231.39 1243,3231.39 1237,3225.39 1237,3149.39 1245,3141.39 1979,3141.39 2013,3175.39 2013,3457.39 1985,3485.39 1882,3485.39 1816,3419.39 1326,3419.39 1320,3413.39
Vin on Bottom Layer "Bottom Layer-No Net 7" (solid, remove dead copper, pour order 1186): 1747,4077.39 1766,4058.39 1828,4058.39 1853,4083.39 1853,4209.39 1826,4236.39 1754,4236.39 1747,4229.39
PWRGND03 on Bottom Layer "Bottom Layer-No Net 9" (solid, remove dead copper, pour order 1184): 1002,2937.39 1008,2931.39 1155,2931.39 1169,2945.39 1169,3028.39 1162,3035.39 1010,3035.39 1002,3027.39
NetC66_1 on Bottom Layer "Bottom Layer-No Net 8" (solid, remove dead copper, pour order 1150): 1560,2689.69 1580,2669.69 1580,2620.69 1595,2605.69 1700,2605.69 1705,2610.69 1705,2726.54 1691.85,2739.69 1578,2739.69 1560,2721.69
NetC50_2 on Bottom Layer "NETC50_2_L04_P1146" (solid, remove dead copper, pour order 1146): 398.74,2675.69 423.74,2650.69 702.74,2650.69 712.74,2660.69 712.74,2748.69 699.74,2761.69 415.74,2761.69 398.74,2744.69
GND on Bottom Layer "Bottom Layer-No Net" (solid, remove dead copper, pour order 1144): 194.74,2251.69 190.74,2247.69 97.31,2247.69 89,2256 89,2587 163,2587 194.74,2555.26
NetD11_3 on Bottom Layer "Bottom Layer-No Net 3" (solid, remove dead copper, pour order 1140): 1031.74,1797.95 1037,1792.69 1289.28,1792.69 1300,1803.42 1300,1975.83 1293.13,1982.69 1040.74,1982.69 1031.74,1973.69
